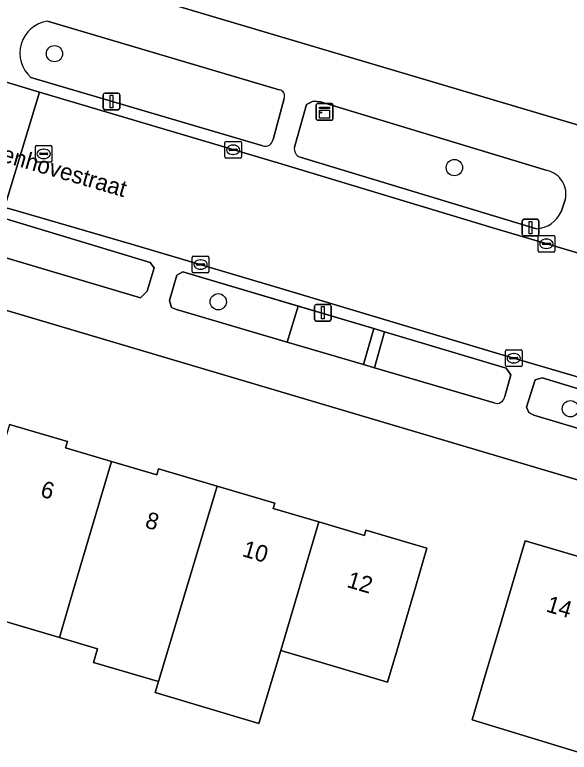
# Model space of a CAD drawing. Extents: x 161771 to 163125, y 382475 to 383179.
# Drawn here: x 162466.13 to 162499.44, y 382587.47 to 382631.78 of the extents above; entities that cross this region are included whole.
import ezdxf

# ---------------------------------------------------------------- set-up
doc = ezdxf.new("R2010")
doc.units = 0
for name, color, linetype in [('IMGEO_Boom', 7, 'Continuous'), ('IMGEO_Erf', 7, 'Continuous'), ('IMGEO_Groenvoorziening', 7, 'Continuous'), ('IMGEO_Haag', 7, 'Continuous'), ('IMGEO_Kast', 7, 'Continuous'), ('IMGEO_Kolk', 7, 'Continuous'), ('IMGEO_Lichtmast', 7, 'Continuous'), ('IMGEO_Openbare_ruimte_label', 7, 'Continuous'), ('IMGEO_Pand', 7, 'Continuous'), ('IMGEO_Pand_nummerreeks', 7, 'Continuous'), ('IMGEO_Rijbaan_lokaal_open', 7, 'Continuous'), ('IMGEO_Rioolput', 7, 'Continuous'), ('IMGEO_Voetpad_open', 7, 'Continuous')]:
    doc.layers.add(name, color=color, linetype=linetype)

msp = doc.modelspace()

# ---------------------------------------------------------------- linework, layer by layer
at = {"layer": 'IMGEO_Boom'}
for centre in [(162468.519, 382629.444), (162492.545, 382622.597), (162478.356, 382614.537), (162499.515, 382608.109)]:
    msp.add_circle(centre, 0.489, dxfattribs=at)
at = {"layer": 'IMGEO_Erf'}
for points in [[(162489.16, 382693.298), (162468.305, 382634.573), (162500, 382625.154)], [(162500, 382603.809), (162455.048, 382617.15)], [(162465.825, 382607.171), (162469.293, 382606.148), (162469.179, 382605.761), (162471.95, 382604.943), (162474.659, 382604.144), (162474.766, 382604.509), (162478.298, 382603.467), (162481.76, 382602.445), (162481.663, 382602.114), (162484.401, 382601.306), (162487.139, 382600.498), (162487.23, 382600.806), (162490.897, 382599.724), (162490.227, 382597.453), (162489.482, 382594.929), (162489.099, 382593.63), (162488.525, 382591.684), (162482.121, 382593.574), (162480.805, 382589.193), (162474.567, 382591.067), (162474.768, 382591.719), (162470.872, 382592.869), (162471.111, 382593.68), (162468.814, 382594.358), (162462.574, 382596.199)], [(162499.972, 382587.47), (162493.607, 382589.411), (162494.401, 382592.081), (162495.394, 382595.434), (162496.795, 382600.167), (162500.2, 382599.163)]]:
    msp.add_lwpolyline(points, dxfattribs=at)
at = {"layer": 'IMGEO_Groenvoorziening'}
for points in [[(162482.025, 382627.277), (162468.097, 382631.398)], [(162467.108, 382628.015), (162481.042, 382623.902)], [(162481.651, 382624.287), (162482.311, 382626.751)], [(162484.505, 382626.555), (162484.063, 382626.583), (162483.661, 382626.396), (162482.939, 382623.824)], [(162498.113, 382622.422), (162484.505, 382626.555)], [(162483.272, 382623.234), (162497.476, 382618.919)], [(162498.961, 382619.95), (162499.207, 382620.658)], [(162495.57, 382608.837), (162495.931, 382610.138), (162495.651, 382610.555), (162488.352, 382612.727), (162487.743, 382610.574), (162494.93, 382608.464)]]:
    msp.add_lwpolyline(points, dxfattribs=at)
for points in [[(162463.638, 382617.759), (162473.691, 382614.776), (162474.08, 382615.166), (162474.502, 382616.576), (162474.273, 382616.902), (162464.247, 382619.912)], [(162483.158, 382614.273), (162476.238, 382616.333), (162475.873, 382616.132), (162475.436, 382614.622), (162475.545, 382614.197), (162475.844, 382614.066), (162482.5, 382612.112)], [(162487.695, 382612.923), (162483.158, 382614.273), (162482.5, 382612.112), (162487.085, 382610.767)], [(162504.997, 382605.447), (162505.607, 382607.605), (162500, 382609.311), (162497.825, 382609.961), (162497.392, 382609.851), (162496.877, 382608.204), (162497.009, 382607.89), (162497.311, 382607.733), (162500, 382606.917)]]:
    msp.add_lwpolyline(points, close=True, dxfattribs=at)
for centre, radius, start, end in [((162468.379, 382629.479), 1.939, 98.3665, 229.0416), ((162481.974, 382626.909), 0.372, 334.9283, 82.1399), ((162481.179, 382624.36), 0.478, 253.3922, 351.2086), ((162483.432, 382623.713), 0.505, 167.3614, 251.52), ((162497.796, 382621.004), 1.453, 346.2256, 77.3872), ((162497.359, 382620.673), 1.757, 273.8193, 335.7234), ((162495.102, 382608.905), 0.473, 248.6961, 351.7722)]:
    msp.add_arc(centre, radius, start, end, dxfattribs=at)
at = {"layer": 'IMGEO_Haag'}
for points in [[(162482.025, 382627.277), (162468.097, 382631.398)], [(162467.108, 382628.015), (162481.042, 382623.902)], [(162481.651, 382624.287), (162482.311, 382626.751)], [(162484.505, 382626.555), (162484.063, 382626.583), (162483.661, 382626.396), (162482.939, 382623.824)], [(162498.113, 382622.422), (162484.505, 382626.555)], [(162483.272, 382623.234), (162497.476, 382618.919)], [(162498.961, 382619.95), (162499.207, 382620.658)], [(162495.57, 382608.837), (162495.931, 382610.138), (162495.651, 382610.555), (162488.352, 382612.727), (162487.743, 382610.574), (162494.93, 382608.464)]]:
    msp.add_lwpolyline(points, dxfattribs=at)
for points in [[(162463.638, 382617.759), (162473.691, 382614.776), (162474.08, 382615.166), (162474.502, 382616.576), (162474.273, 382616.902), (162464.247, 382619.912)], [(162487.695, 382612.923), (162476.238, 382616.333), (162475.873, 382616.132), (162475.436, 382614.622), (162475.545, 382614.197), (162475.844, 382614.066), (162487.085, 382610.767)], [(162504.997, 382605.447), (162505.607, 382607.605), (162500, 382609.311), (162497.825, 382609.961), (162497.392, 382609.851), (162496.877, 382608.204), (162497.009, 382607.89), (162497.311, 382607.733), (162500, 382606.917)]]:
    msp.add_lwpolyline(points, close=True, dxfattribs=at)
for centre, radius, start, end in [((162468.379, 382629.479), 1.939, 98.3665, 229.0416), ((162481.974, 382626.909), 0.372, 334.9283, 82.1399), ((162481.179, 382624.36), 0.478, 253.3922, 351.2086), ((162483.432, 382623.713), 0.505, 167.3614, 251.52), ((162497.796, 382621.004), 1.453, 346.2256, 77.3872), ((162497.359, 382620.673), 1.757, 273.8193, 335.7234), ((162495.102, 382608.905), 0.473, 248.6961, 351.7722)]:
    msp.add_arc(centre, radius, start, end, dxfattribs=at)
at = {"layer": 'IMGEO_Kast'}
for p, q in [((162484.246, 382625.518), (162484.246, 382626.359)), ((162484.246, 382626.359), (162484.246, 382625.518)), ((162484.321, 382626.443), (162485.162, 382626.443)), ((162485.162, 382626.443), (162484.321, 382626.443)), ((162485.246, 382626.368), (162485.246, 382625.527)), ((162485.246, 382625.527), (162485.246, 382626.368)), ((162485.171, 382625.443), (162484.33, 382625.443)), ((162484.33, 382625.443), (162485.171, 382625.443))]:
    msp.add_line(p, q, dxfattribs=at)
for points in [[(162484.441, 382626.233), (162485.041, 382626.233), (162485.041, 382626.148), (162484.441, 382626.148), (162484.441, 382626.233)], [(162484.441, 382626.058), (162485.041, 382626.058), (162485.041, 382625.569), (162484.441, 382625.569), (162484.441, 382626.058)]]:
    msp.add_lwpolyline(points, dxfattribs=at)
msp.add_circle((162484.525, 382625.907), 0.0377, dxfattribs=at)
for centre, start, end in [((162484.324, 382626.365), 92.4484, 184.2845), ((162484.324, 382626.365), 92.4484, 184.2845), ((162485.168, 382626.365), 2.4484, 94.2845), ((162485.168, 382626.365), 2.4484, 94.2845), ((162484.324, 382625.521), 182.4484, 274.2845), ((162484.324, 382625.521), 182.4484, 274.2845), ((162485.168, 382625.521), 272.4484, 4.2845), ((162485.168, 382625.521), 272.4484, 4.2845)]:
    msp.add_arc(centre, 0.0779, start, end, dxfattribs=at)
at = {"layer": 'IMGEO_Kolk'}
for p, q in [((162478.751, 382623.246), (162478.751, 382624.098)), ((162478.826, 382624.172), (162479.678, 382624.172)), ((162479.239, 382623.952), (162479.264, 382623.952)), ((162479.752, 382624.098), (162479.752, 382623.246)), ((162479.01, 382623.666), (162479.01, 382623.678)), ((162479.448, 382623.629), (162479.05, 382623.629)), ((162479.053, 382623.715), (162479.451, 382623.715)), ((162479.262, 382623.392), (162479.237, 382623.392)), ((162479.494, 382623.678), (162479.494, 382623.666)), ((162479.678, 382623.172), (162478.826, 382623.172)), ((162497.645, 382618.523), (162498.497, 382618.523)), ((162497.57, 382617.597), (162497.57, 382618.449)), ((162497.872, 382618.066), (162498.27, 382618.066)), ((162498.058, 382618.303), (162498.083, 382618.303)), ((162498.571, 382618.449), (162498.571, 382617.597)), ((162497.829, 382618.017), (162497.829, 382618.029)), ((162498.267, 382617.98), (162497.869, 382617.98)), ((162498.081, 382617.743), (162498.056, 382617.743)), ((162498.313, 382618.029), (162498.313, 382618.017)), ((162476.796, 382616.346), (162476.796, 382617.198)), ((162476.871, 382617.272), (162477.723, 382617.272)), ((162477.797, 382617.198), (162477.797, 382616.346)), ((162498.497, 382617.523), (162497.645, 382617.523)), ((162477.055, 382616.766), (162477.055, 382616.778)), ((162477.493, 382616.729), (162477.095, 382616.729)), ((162477.098, 382616.815), (162477.496, 382616.815)), ((162477.284, 382617.052), (162477.309, 382617.052)), ((162477.539, 382616.778), (162477.539, 382616.766)), ((162477.723, 382616.272), (162476.871, 382616.272)), ((162477.307, 382616.492), (162477.282, 382616.492)), ((162495.612, 382610.716), (162495.612, 382611.568)), ((162495.687, 382611.642), (162496.539, 382611.642)), ((162496.1, 382611.422), (162496.125, 382611.422)), ((162496.613, 382611.568), (162496.613, 382610.716)), ((162495.871, 382611.136), (162495.871, 382611.148)), ((162496.309, 382611.099), (162495.911, 382611.099)), ((162495.914, 382611.185), (162496.312, 382611.185)), ((162496.355, 382611.148), (162496.355, 382611.136)), ((162496.539, 382610.642), (162495.687, 382610.642)), ((162496.123, 382610.862), (162496.098, 382610.862))]:
    msp.add_line(p, q, dxfattribs=at)
for points in [[(162478.751, 382623.246), (162478.751, 382624.098)], [(162478.826, 382624.172), (162479.678, 382624.172)], [(162479.752, 382624.098), (162479.752, 382623.246)], [(162479.678, 382623.172), (162478.826, 382623.172)], [(162497.645, 382618.523), (162498.497, 382618.523)], [(162497.57, 382617.597), (162497.57, 382618.449)], [(162498.571, 382618.449), (162498.571, 382617.597)], [(162476.796, 382616.346), (162476.796, 382617.198)], [(162476.871, 382617.272), (162477.723, 382617.272)], [(162477.797, 382617.198), (162477.797, 382616.346)], [(162498.497, 382617.523), (162497.645, 382617.523)], [(162477.723, 382616.272), (162476.871, 382616.272)], [(162495.612, 382610.716), (162495.612, 382611.568)], [(162495.687, 382611.642), (162496.539, 382611.642)], [(162496.613, 382611.568), (162496.613, 382610.716)], [(162496.539, 382610.642), (162495.687, 382610.642)]]:
    msp.add_lwpolyline(points, dxfattribs=at)
for centre, radius, start, end in [((162478.828, 382624.096), 0.0765, 91.552, 178.448), ((162478.828, 382624.096), 0.0765, 91.552, 178.448), ((162479.676, 382624.096), 0.0765, 1.552, 88.448), ((162479.676, 382624.096), 0.0765, 1.552, 88.448), ((162479.05, 382623.675), 0.0403, 85.8775, 175.7526), ((162479.047, 382623.665), 0.0366, 178.938, 274.7102), ((162479.451, 382623.672), 0.043, 264.8664, 352.4533), ((162479.455, 382623.677), 0.0386, 1.7309, 96.639), ((162478.828, 382623.248), 0.0765, 181.552, 268.448), ((162478.828, 382623.248), 0.0765, 181.552, 268.448), ((162479.676, 382623.248), 0.0765, 271.552, 358.448), ((162479.676, 382623.248), 0.0765, 271.552, 358.448), ((162497.647, 382618.447), 0.0765, 91.552, 178.448), ((162497.647, 382618.447), 0.0765, 91.552, 178.448), ((162498.495, 382618.447), 0.0765, 1.552, 88.448), ((162498.495, 382618.447), 0.0765, 1.552, 88.448), ((162497.869, 382618.026), 0.0403, 85.8775, 175.7526), ((162498.274, 382618.028), 0.0386, 1.7309, 96.639), ((162497.866, 382618.016), 0.0366, 178.938, 274.7102), ((162498.27, 382618.023), 0.043, 264.8664, 352.4533), ((162476.873, 382617.196), 0.0765, 91.552, 178.448), ((162476.873, 382617.196), 0.0765, 91.552, 178.448), ((162477.721, 382617.196), 0.0765, 1.552, 88.448), ((162477.721, 382617.196), 0.0765, 1.552, 88.448), ((162497.647, 382617.599), 0.0765, 181.552, 268.448), ((162497.647, 382617.599), 0.0765, 181.552, 268.448), ((162498.495, 382617.599), 0.0765, 271.552, 358.448), ((162498.495, 382617.599), 0.0765, 271.552, 358.448), ((162477.095, 382616.775), 0.0403, 85.8775, 175.7526), ((162477.092, 382616.765), 0.0366, 178.938, 274.7102), ((162477.496, 382616.772), 0.043, 264.8664, 352.4533), ((162477.5, 382616.777), 0.0386, 1.7309, 96.639), ((162476.873, 382616.348), 0.0765, 181.552, 268.448), ((162476.873, 382616.348), 0.0765, 181.552, 268.448), ((162477.721, 382616.348), 0.0765, 271.552, 358.448), ((162477.721, 382616.348), 0.0765, 271.552, 358.448), ((162495.689, 382611.566), 0.0765, 91.552, 178.448), ((162495.689, 382611.566), 0.0765, 91.552, 178.448), ((162496.537, 382611.566), 0.0765, 1.552, 88.448), ((162496.537, 382611.566), 0.0765, 1.552, 88.448), ((162495.911, 382611.145), 0.0403, 85.8775, 175.7526), ((162495.908, 382611.135), 0.0366, 178.938, 274.7102), ((162496.312, 382611.142), 0.043, 264.8664, 352.4533), ((162496.316, 382611.147), 0.0386, 1.7309, 96.639), ((162495.689, 382610.718), 0.0765, 181.552, 268.448), ((162495.689, 382610.718), 0.0765, 181.552, 268.448), ((162496.537, 382610.718), 0.0765, 271.552, 358.448), ((162496.537, 382610.718), 0.0765, 271.552, 358.448)]:
    msp.add_arc(centre, radius, start, end, dxfattribs=at)
for centre, major_axis, ratio, start_param, end_param in [((162479.238, 382623.672), (-0.387, 0.002), 0.722429, 4.712389, 7.853982), ((162479.263, 382623.672), (-0.39, 0.002), 0.717154, 1.570796, 4.712389), ((162498.057, 382618.023), (-0.387, 0.002), 0.722429, 4.712389, 7.853982), ((162498.082, 382618.023), (-0.39, 0.002), 0.717154, 1.570796, 4.712389), ((162477.283, 382616.772), (-0.387, 0.002), 0.722429, 4.712389, 7.853982), ((162477.308, 382616.772), (-0.39, 0.002), 0.717154, 1.570796, 4.712389), ((162496.099, 382611.142), (-0.387, 0.002), 0.722429, 4.712389, 7.853982), ((162496.124, 382611.142), (-0.39, 0.002), 0.717154, 1.570796, 4.712389)]:
    msp.add_ellipse(centre, major_axis=major_axis, ratio=ratio, start_param=start_param, end_param=end_param, dxfattribs=at)
at = {"layer": 'IMGEO_Lichtmast'}
for p, q in [((162471.453, 382626.173), (162471.453, 382626.973)), ((162471.453, 382626.973), (162471.453, 382626.173)), ((162471.553, 382627.073), (162472.343, 382627.073)), ((162472.343, 382627.073), (162471.553, 382627.073)), ((162472.443, 382626.973), (162472.443, 382626.173)), ((162472.443, 382626.173), (162472.443, 382626.973)), ((162472.343, 382626.073), (162471.553, 382626.073)), ((162471.553, 382626.073), (162472.343, 382626.073)), ((162496.621, 382618.594), (162496.621, 382619.394)), ((162496.621, 382619.394), (162496.621, 382618.594)), ((162496.721, 382619.494), (162497.511, 382619.494)), ((162497.511, 382619.494), (162496.721, 382619.494)), ((162497.611, 382619.394), (162497.611, 382618.594)), ((162497.611, 382618.594), (162497.611, 382619.394)), ((162497.511, 382618.494), (162496.721, 382618.494)), ((162496.721, 382618.494), (162497.511, 382618.494)), ((162484.15, 382613.477), (162484.15, 382614.277)), ((162484.15, 382614.277), (162484.15, 382613.477)), ((162484.25, 382614.377), (162485.04, 382614.377)), ((162485.04, 382614.377), (162484.25, 382614.377)), ((162485.14, 382614.277), (162485.14, 382613.477)), ((162485.14, 382613.477), (162485.14, 382614.277)), ((162485.04, 382613.377), (162484.25, 382613.377)), ((162484.25, 382613.377), (162485.04, 382613.377))]:
    msp.add_line(p, q, dxfattribs=at)
for points in [[(162471.873, 382626.948), (162472.023, 382626.948), (162472.023, 382626.198), (162471.873, 382626.198), (162471.873, 382626.948)], [(162497.041, 382619.369), (162497.191, 382619.369), (162497.191, 382618.619), (162497.041, 382618.619), (162497.041, 382619.369)], [(162484.57, 382614.252), (162484.72, 382614.252), (162484.72, 382613.502), (162484.57, 382613.502), (162484.57, 382614.252)]]:
    msp.add_lwpolyline(points, dxfattribs=at)
for centre, start, end in [((162471.553, 382626.973), 90, 180), ((162471.553, 382626.973), 90, 180), ((162472.343, 382626.973), 0, 90), ((162472.343, 382626.973), 360, 90), ((162471.553, 382626.173), 180, 270), ((162471.553, 382626.173), 180, 270), ((162472.343, 382626.173), 270, 0), ((162472.343, 382626.173), 270, 0), ((162496.721, 382619.394), 90, 180), ((162496.721, 382619.394), 90, 180), ((162497.511, 382619.394), 0, 90), ((162497.511, 382619.394), 360, 90), ((162496.721, 382618.594), 180, 270), ((162496.721, 382618.594), 180, 270), ((162497.511, 382618.594), 270, 0), ((162497.511, 382618.594), 270, 0), ((162484.25, 382614.277), 90, 180), ((162484.25, 382614.277), 90, 180), ((162485.04, 382614.277), 0, 90), ((162485.04, 382614.277), 360, 90), ((162484.25, 382613.477), 180, 270), ((162484.25, 382613.477), 180, 270), ((162485.04, 382613.477), 270, 0), ((162485.04, 382613.477), 270, 0)]:
    msp.add_arc(centre, 0.1, start, end, dxfattribs=at)
at = {"layer": 'IMGEO_Pand'}
for points in [[(162471.95, 382604.943), (162469.179, 382605.761), (162469.293, 382606.148), (162465.825, 382607.171), (162463.427, 382599.091), (162462.574, 382596.199), (162468.814, 382594.358), (162469.667, 382597.249)], [(162469.667, 382597.249), (162468.814, 382594.358), (162471.111, 382593.68), (162470.872, 382592.869), (162474.768, 382591.719), (162478.298, 382603.467), (162474.766, 382604.509), (162474.659, 382604.144), (162471.95, 382604.943)], [(162484.401, 382601.306), (162481.663, 382602.114), (162481.76, 382602.445), (162478.298, 382603.467), (162474.768, 382591.719), (162474.567, 382591.067), (162480.805, 382589.193), (162482.121, 382593.574)], [(162490.227, 382597.453), (162490.897, 382599.724), (162487.23, 382600.806), (162487.139, 382600.498), (162484.401, 382601.306), (162482.121, 382593.574), (162488.525, 382591.684), (162489.099, 382593.63), (162489.482, 382594.929)], [(162503.068, 382597.989), (162500.379, 382598.78), (162500.468, 382599.085), (162500.2, 382599.163), (162496.795, 382600.167), (162495.394, 382595.434), (162494.401, 382592.081), (162493.607, 382589.411), (162499.972, 382587.47), (162500.748, 382590.213)]]:
    msp.add_lwpolyline(points, close=True, dxfattribs=at)
at = {"layer": 'IMGEO_Rijbaan_lokaal_open'}
msp.add_lwpolyline([(162464.806, 382627.963), (162462.766, 382621.026), (162465.52, 382620.21), (162467.619, 382627.127)], close=True, dxfattribs=at)
msp.add_lwpolyline([(162500, 382617.448), (162494.86, 382618.975), (162482.134, 382622.815), (162467.619, 382627.127), (162465.52, 382620.21), (162465.918, 382620.092), (162473.151, 382618.001), (162482.258, 382615.302), (162488.259, 382613.491), (162495.213, 382611.406), (162500, 382610.003)], dxfattribs=at)
at = {"layer": 'IMGEO_Rioolput'}
for p, q in [((162467.369, 382622.998), (162467.369, 382623.85)), ((162467.444, 382623.924), (162468.296, 382623.924)), ((162468.37, 382623.85), (162468.37, 382622.998)), ((162467.628, 382623.418), (162467.628, 382623.43)), ((162468.066, 382623.381), (162467.668, 382623.381)), ((162467.671, 382623.467), (162468.069, 382623.467)), ((162467.857, 382623.704), (162467.882, 382623.704)), ((162468.112, 382623.43), (162468.112, 382623.418)), ((162468.296, 382622.924), (162467.444, 382622.924)), ((162467.88, 382623.144), (162467.855, 382623.144))]:
    msp.add_line(p, q, dxfattribs=at)
for points in [[(162467.369, 382622.998), (162467.369, 382623.85)], [(162467.444, 382623.924), (162468.296, 382623.924)], [(162468.37, 382623.85), (162468.37, 382622.998)], [(162468.296, 382622.924), (162467.444, 382622.924)]]:
    msp.add_lwpolyline(points, dxfattribs=at)
for centre, radius, start, end in [((162467.446, 382623.848), 0.0765, 91.552, 178.448), ((162467.446, 382623.848), 0.0765, 91.552, 178.448), ((162468.294, 382623.848), 0.0765, 1.552, 88.448), ((162468.294, 382623.848), 0.0765, 1.552, 88.448), ((162467.668, 382623.427), 0.0403, 85.8775, 175.7526), ((162467.665, 382623.417), 0.0366, 178.938, 274.7102), ((162468.069, 382623.424), 0.043, 264.8664, 352.4533), ((162468.073, 382623.429), 0.0386, 1.7309, 96.639), ((162467.446, 382623), 0.0765, 181.552, 268.448), ((162467.446, 382623), 0.0765, 181.552, 268.448), ((162468.294, 382623), 0.0765, 271.552, 358.448), ((162468.294, 382623), 0.0765, 271.552, 358.448)]:
    msp.add_arc(centre, radius, start, end, dxfattribs=at)
for centre, major_axis, ratio, start_param, end_param in [((162467.856, 382623.424), (-0.387, 0.002), 0.722429, 4.712389, 7.853982), ((162467.881, 382623.424), (-0.39, 0.002), 0.717154, 1.570796, 4.712389)]:
    msp.add_ellipse(centre, major_axis=major_axis, ratio=ratio, start_param=start_param, end_param=end_param, dxfattribs=at)
at = {"layer": 'IMGEO_Voetpad_open'}
for points in [[(162562.442, 382606.621), (162559.118, 382607.586), (162531.953, 382615.658), (162530.512, 382616.086), (162505.275, 382623.586), (162500.101, 382625.124), (162500, 382625.154), (162468.305, 382634.573), (162463.814, 382636.141), (162462.978, 382633.835)], [(162468.097, 382631.398), (162482.025, 382627.277)], [(162454.793, 382630.882), (162464.806, 382627.963), (162467.619, 382627.127), (162482.134, 382622.815), (162494.86, 382618.975), (162500, 382617.448), (162508.43, 382614.944), (162520.385, 382611.423), (162531.476, 382608.135), (162540.02, 382605.594), (162542.72, 382604.802), (162545.474, 382603.995), (162547.986, 382603.221), (162553.952, 382601.516)], [(162481.042, 382623.902), (162467.108, 382628.015)], [(162482.311, 382626.751), (162481.651, 382624.287)], [(162482.939, 382623.824), (162483.661, 382626.396), (162484.063, 382626.583), (162484.505, 382626.555), (162498.113, 382622.422)], [(162497.476, 382618.919), (162483.272, 382623.234)], [(162456.755, 382622.162), (162463.538, 382620.125), (162464.247, 382619.912), (162474.273, 382616.902), (162474.502, 382616.576), (162474.08, 382615.166), (162473.691, 382614.776), (162463.638, 382617.759), (162462.929, 382617.97), (162455.983, 382620.031)], [(162445.062, 382620.114), (162453.051, 382617.743), (162455.048, 382617.15), (162500, 382603.809), (162523.009, 382596.98), (162524.771, 382596.654), (162526.032, 382601.803), (162526.168, 382602.283), (162521.553, 382603.645), (162514.527, 382605.641), (162510.024, 382607.015), (162502.604, 382609.24), (162500, 382610.003), (162495.213, 382611.406), (162488.259, 382613.491), (162482.258, 382615.302), (162473.151, 382618.001), (162465.918, 382620.092), (162465.52, 382620.21), (162462.766, 382621.026)], [(162499.207, 382620.658), (162498.961, 382619.95)], [(162475.873, 382616.132), (162476.238, 382616.333), (162483.158, 382614.273), (162487.695, 382612.923), (162488.352, 382612.727), (162495.651, 382610.555), (162495.931, 382610.138), (162495.57, 382608.837)], [(162494.93, 382608.464), (162487.743, 382610.574), (162487.085, 382610.767), (162482.5, 382612.112), (162475.844, 382614.066), (162475.545, 382614.197), (162475.436, 382614.622), (162475.873, 382616.132)]]:
    msp.add_lwpolyline(points, dxfattribs=at)
for points in [[(162487.743, 382610.574), (162488.352, 382612.727), (162487.695, 382612.923), (162487.085, 382610.767)], [(162497.392, 382609.851), (162497.825, 382609.961), (162500, 382609.311), (162505.607, 382607.605), (162506.24, 382607.412), (162510.799, 382606.025), (162511.052, 382605.668), (162510.563, 382604.036), (162510.188, 382603.92), (162505.632, 382605.26), (162504.997, 382605.447), (162500, 382606.917), (162497.311, 382607.733), (162497.009, 382607.89), (162496.877, 382608.204)]]:
    msp.add_lwpolyline(points, close=True, dxfattribs=at)
for centre, radius, start, end in [((162468.379, 382629.479), 1.939, 98.3665, 229.0416), ((162481.974, 382626.909), 0.372, 334.9283, 82.1399), ((162481.179, 382624.36), 0.478, 253.3922, 351.2086), ((162483.432, 382623.713), 0.505, 167.3614, 251.52), ((162497.796, 382621.004), 1.453, 346.2256, 77.3872), ((162497.359, 382620.673), 1.757, 273.8193, 335.7234), ((162495.102, 382608.905), 0.473, 248.6961, 351.7722)]:
    msp.add_arc(centre, radius, start, end, dxfattribs=at)

# ---------------------------------------------------------------- texts
at = {"layer": 'IMGEO_Openbare_ruimte_label'}
msp.add_text('van Wassenhovestraat', height=1, rotation=343.6848, dxfattribs=at).set_placement((162459.624, 382624.635))
at = {"layer": 'IMGEO_Pand_nummerreeks'}
for s, rotation, p in [('6', 343.5332, (162467.614, 382602.851)), ('8', 343.5338, (162473.903, 382600.992)), ('10', 343.5338, (162479.746, 382599.264)), ('12', 343.5332, (162486.025, 382597.409)), ('14', 343.4874, (162497.998, 382595.941))]:
    msp.add_text(s, height=1, rotation=rotation, dxfattribs=at).set_placement(p)

doc.saveas('drawing.dxf')
